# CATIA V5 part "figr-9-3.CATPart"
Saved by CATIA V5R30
Part number: Part1
Bounding box of the stored display mesh (mm): x -25 to 69.61, y -164.735 to 0, z 0 to 45
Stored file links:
  D:\PROJECTS\CATIA V56R 2020\Resources\Parts File\c09_catia_v5_6r2020_prt\figr-9-3.CATPart
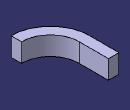
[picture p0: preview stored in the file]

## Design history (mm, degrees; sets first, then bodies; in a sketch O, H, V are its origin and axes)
Body1 (main body)
  Sketch1 on xy-plane, origin (0, 0, 0), H (1, 0, 0), V (0, 1, 0)
    line L1 (0, 0) -> (0, -70.1255)
    arc A1 centre (69.6095, -70.1255) radius 69.6095 from (0, -70.1255) to (69.6095, -139.7351) ccw
    vertical: L1 V
    tangency: A1 L1
  Sketch2 on zx-plane, origin (0, 0, 0), H (-1, 0, 0), V (0, 0, 1)
    point P1 (0, 0)
    line L1 (0, 0) -> (25, 0)
    line L2 (25, 0) -> (25, 45)
    line L3 (25, 45) -> (0, 45)
    line L4 (0, 45) -> (0, 0)
    length L3 = 25
    length L2 = 45
    coincidence: P1 H, P1 O
    horizontal: L1 H, L3 H
    vertical: L2 V, L4 V
  Rib1: profile Sketch2, centre curve Sketch1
